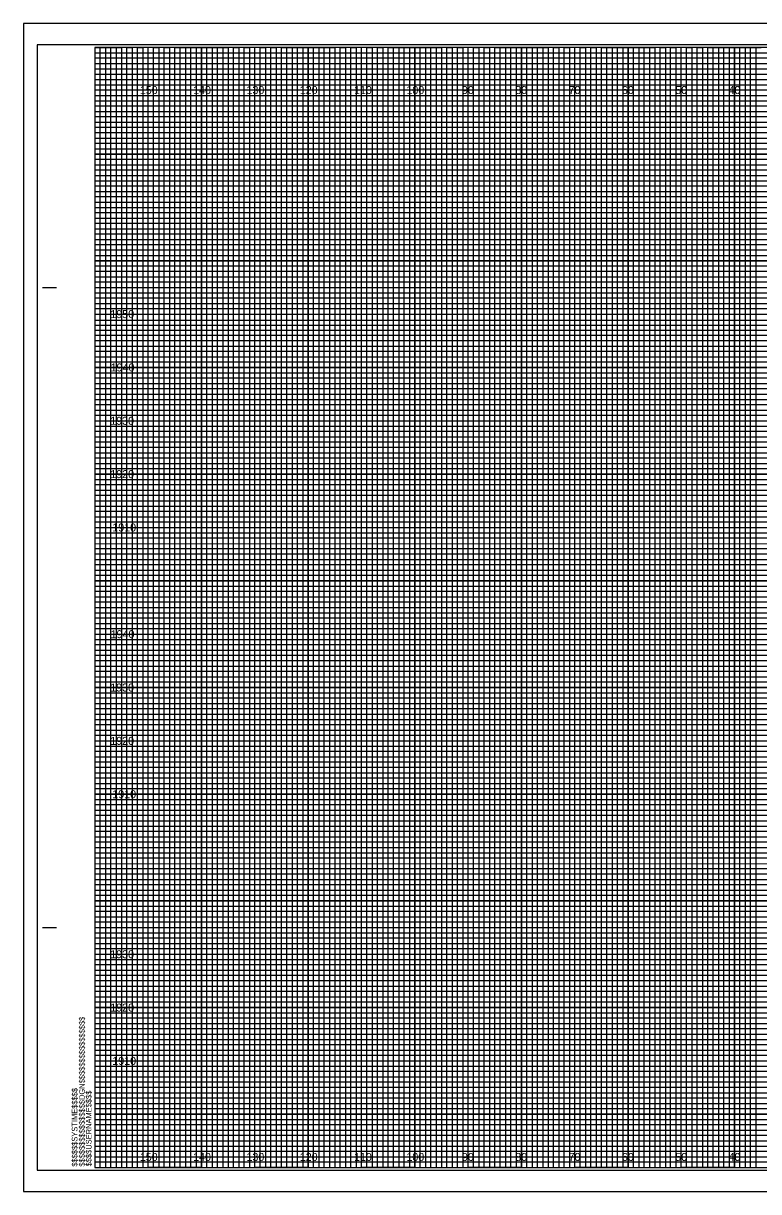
# Model space of a CAD drawing. Extents: x -13 to 323, y -4 to 214.
# Drawn here: x -13.4 to 124.5, y -4.5 to 214.5 of the extents above; entities that cross this region are included whole.
import ezdxf

# ---------------------------------------------------------------- set-up
doc = ezdxf.new("R2010")
doc.units = 0
for name, color, linetype in [('Prop XS Elevation Labels', 7, 'Continuous'), ('Prop XS Offset Labels', 7, 'Continuous'), ('Sheet Cross Section CELL', 7, 'Continuous'), ('Sheet Cross Section Grid Major CELL', 7, 'Continuous'), ('Sheet Cross Section Grid Middle CELL', 7, 'Continuous'), ('Sheet Cross Section Grid Minor 1 CELL', 7, 'Continuous'), ('Sheet Cross Section Grid Minor 2 CELL', 7, 'Continuous'), ('Sheet Cutting Line CELL', 7, 'Continuous'), ('Sheet DOT Grid CELL', 7, 'Continuous'), ('Sheet Plot Border Inside CELL', 7, 'Continuous'), ('Sheet Plot Border Outside CELL', 7, 'Continuous')]:
    doc.layers.add(name, color=color, linetype=linetype)

msp = doc.modelspace()

# ---------------------------------------------------------------- linework, layer by layer
at = {"layer": 'Sheet Cross Section CELL'}
for p, q in [((-9.8, 165), (-7.3, 165)), ((-9.7, 165), (-7.2, 165)), ((-9.8, 45), (-7.3, 45)), ((-9.7, 45), (-7.2, 45))]:
    msp.add_line(p, q, dxfattribs=at)
msp.add_lwpolyline([(320, 210), (0, 210), (0, 0), (320, 0)], close=True, dxfattribs=at)
at = {"layer": 'Sheet Cross Section Grid Major CELL'}
for p, q in [((10, 210), (0, 210)), ((10, 0), (10, 210)), ((30, 210), (20, 210)), ((20, 210), (20, 0)), ((30, 0), (30, 210)), ((50, 210), (40, 210)), ((40, 210), (40, 0)), ((50, 0), (50, 210)), ((70, 210), (60, 210)), ((60, 210), (60, 0)), ((70, 0), (70, 210)), ((90, 210), (80, 210)), ((80, 210), (80, 0)), ((90, 0), (90, 210)), ((110, 210), (100, 210)), ((100, 210), (100, 0)), ((110, 0), (110, 210)), ((130, 210), (120, 210)), ((120, 210), (120, 0)), ((20, 0), (10, 0)), ((40, 0), (30, 0)), ((60, 0), (50, 0)), ((80, 0), (70, 0)), ((100, 0), (90, 0)), ((120, 0), (110, 0))]:
    msp.add_line(p, q, dxfattribs=at)
for points in [[(0, 200), (320, 200), (320, 190), (0, 190)], [(0, 180), (320, 180), (320, 170), (0, 170)], [(0, 160), (320, 160), (320, 150), (0, 150)], [(0, 140), (320, 140), (320, 130), (0, 130)], [(0, 120), (320, 120), (320, 110), (0, 110)], [(0, 100), (320, 100), (320, 90), (0, 90)], [(0, 80), (320, 80), (320, 70), (0, 70)], [(0, 60), (320, 60), (320, 50), (0, 50)], [(0, 40), (320, 40), (320, 30), (0, 30)], [(0, 20), (320, 20), (320, 10), (0, 10)]]:
    msp.add_lwpolyline(points, dxfattribs=at)
at = {"layer": 'Sheet Cross Section Grid Middle CELL'}
for points in [[(0, 210), (5, 210), (5, 0), (15, 0), (15, 210), (25, 210), (25, 0), (35, 0), (35, 210), (45, 210), (45, 0), (55, 0), (55, 210), (65, 210), (65, 0), (75, 0), (75, 210), (85, 210), (85, 0), (95, 0), (95, 210), (105, 210), (105, 0), (115, 0), (115, 210), (125, 210)], [(0, 205), (275, 205)], [(0, 185), (320, 185), (320, 195), (0, 195)], [(0, 165), (320, 165), (320, 175), (0, 175)], [(0, 145), (320, 145), (320, 155), (0, 155)], [(0, 125), (320, 125), (320, 135), (0, 135)], [(0, 105), (320, 105), (320, 115), (0, 115)], [(0, 85), (320, 85), (320, 95), (0, 95)], [(0, 65), (320, 65), (320, 75), (0, 75)], [(0, 45), (320, 45), (320, 55), (0, 55)], [(0, 25), (320, 25), (320, 35), (0, 35)], [(0, 5), (320, 5), (320, 15), (0, 15)]]:
    msp.add_lwpolyline(points, dxfattribs=at)
at = {"layer": 'Sheet Cross Section Grid Minor 1 CELL'}
for p, q in [((0, 209), (260, 209)), ((260, 207.98), (0, 207.98)), ((0, 207.98), (0, 207)), ((0, 207), (260, 207)), ((260, 205.89), (0, 205.89)), ((0, 205.89), (0, 204)), ((0, 204), (320, 204))]:
    msp.add_line(p, q, dxfattribs=at)
for points in [[(0, 203), (270, 203), (320, 203), (320, 202), (0, 202)], [(0, 201), (320, 201), (320, 199), (0, 199)], [(0, 198), (320, 198), (320, 197), (0, 196.98)], [(0, 196), (320, 196), (320, 194), (0, 194)], [(0, 193), (320, 193), (320, 192), (0, 192)], [(0, 191), (320, 191), (320, 189), (0, 189)], [(0, 188), (320, 188), (320, 187), (0, 187)], [(0, 186), (320, 186), (320, 184), (0, 184)], [(0, 183), (320, 183), (320, 182), (0, 182)], [(0, 181), (320, 181), (320, 179), (0, 179)], [(0, 178), (320, 178), (320, 177), (0, 177)], [(0, 176), (320, 176), (320, 173.95), (320, 173), (320, 172), (0, 172)], [(0, 174), (320, 174), (320, 173), (0, 173)], [(0, 171), (320, 171), (320, 169), (0, 169.03)], [(0, 169.03), (320, 169), (320, 168), (0, 168)], [(0, 167), (320, 167), (320, 166), (0, 166)], [(0, 164), (320, 164), (320, 163), (0, 163)], [(0, 162), (320, 162), (320, 161), (0, 161)], [(-0.07, 158.89), (320, 158.89), (320, 157.88), (-0.07, 157.88)], [(0, 157), (320, 157), (320, 156), (0, 156)], [(0, 154), (320, 154), (320, 153), (0, 153)], [(0, 152), (320, 152), (320, 151), (0, 151)], [(0, 149), (320, 149), (320, 148), (0, 148)], [(0, 147), (320, 147), (320, 146), (0, 146)], [(0, 144), (320, 144), (320, 143), (0, 143)], [(0, 142), (320, 142), (320, 141), (0, 141)], [(0, 139), (320, 139), (319.99, 137.98), (0, 138)], [(0, 137), (320, 137), (320, 136), (0, 136)], [(0, 134), (320, 134), (320, 133), (0, 133)], [(0, 132), (320, 132), (320, 131), (0, 131)], [(0, 129), (320, 129), (320, 128), (0, 128)], [(0, 127), (320, 127), (320, 126), (0, 126)], [(0, 124), (320, 124), (320, 123), (0, 123)], [(0, 122), (320, 122), (320, 121), (0, 121)], [(0, 119), (320, 119), (320, 118), (0, 118)], [(0, 116.99), (320.07, 116.91), (320, 116), (0, 116)], [(0, 114), (320, 114), (320, 113), (0, 113)], [(0, 112), (320, 112), (320, 111), (0, 111)], [(0, 109), (320, 109), (320, 108), (0, 108)], [(0, 107), (320, 107), (320, 106), (0, 106)], [(0, 104), (320, 104), (320, 103), (0, 103)], [(0, 102), (320, 102), (320, 101), (0, 101)], [(0, 99), (320, 99), (320, 98), (0, 98)], [(0, 97), (320, 97), (320, 96), (0, 96)], [(0, 94), (320, 94), (320, 93), (0, 93)], [(0, 92), (320, 92), (320, 91), (0, 91)], [(0, 89), (320, 89), (320, 88), (0, 88)], [(0, 87), (320, 87), (320, 86), (0, 86)], [(0, 84), (320, 84), (320, 83), (0, 83)], [(0, 82), (320, 82), (320, 81), (0, 81)], [(0, 79), (320, 79), (319.99, 77.98), (0, 78)], [(0, 77), (320, 77), (320, 76), (0, 76)], [(0, 74), (320, 74), (320, 73), (0, 73)], [(0, 72), (320, 72), (320, 71), (0, 71)], [(0, 69), (320, 69), (320, 68), (0, 68)], [(0, 67), (320, 67), (320, 66), (0, 66)], [(0, 64), (320, 64), (320, 63), (0, 63)], [(0, 62), (320, 62), (320, 61), (0, 61)], [(0, 59), (320, 59), (320, 58), (0, 58)], [(0, 56.99), (320.07, 56.91), (320, 56), (0, 56)], [(0, 54), (320, 54), (320, 53), (0, 53)], [(0, 52), (320, 52), (320, 51), (0, 51)], [(0, 49), (320, 49), (320, 48), (0, 48)], [(0, 47), (320, 47), (320, 46), (0, 46)], [(0, 44), (320, 44), (320, 43), (0, 43)], [(0, 42), (320, 42), (320, 41), (0, 41)], [(0, 39), (320, 39), (320, 38), (0, 38)], [(0, 37), (320, 37), (320, 36), (0, 36)], [(0, 34), (320, 34), (320, 33), (0, 33)], [(0, 32), (320, 32), (320, 31), (0, 31)], [(0, 29), (320, 29), (320, 28), (0, 28)], [(0, 27), (320, 27), (320, 26), (0, 26)], [(0, 24), (320, 24), (320, 23), (0, 23)], [(0, 22), (320, 22), (320, 21), (0, 21)], [(0, 19), (320, 19), (320, 18), (0, 18)], [(0, 17), (320, 17), (320, 16), (0, 16)], [(0, 14), (320, 14), (320, 13), (0, 13)], [(0, 12), (320, 12), (320, 11), (0, 11)], [(0, 9), (320, 9), (320, 8), (0, 8)], [(0, 7), (320, 7), (320, 6), (0, 6)], [(0, 4), (320, 4), (320, 3), (0, 3)], [(0, 2), (320, 2), (320, 1), (0, 1)]]:
    msp.add_lwpolyline(points, dxfattribs=at)
at = {"layer": 'Sheet Cross Section Grid Minor 2 CELL'}
for points in [[(0, 0), (1, 0), (1, 210), (2, 210), (2, 0)], [(2, 0), (3, 0), (3, 210), (4, 210), (4, 0)], [(5, 0), (6, 0), (6, 210), (7, 210), (7, 0)], [(7, 0), (8, 0), (8, 210), (9, 210), (9, 0)], [(10, 0), (11, 0), (11, 210), (12, 210), (12, 0)], [(12, 0), (13, 0), (13, 210), (14, 210), (14, 0)], [(15, 0), (16, 0), (16, 210), (17, 210), (17, 0)], [(17, 0), (18, 0), (18, 210), (19, 210), (19, 0)], [(20, 0), (21, 0), (21, 210), (22, 210), (22, 0)], [(22, 0), (23, 0), (23, 210), (24, 210), (24, 0)], [(25, 0), (26, 0), (26, 210), (27, 210), (27, 0)], [(27, 0), (28, 0), (28, 210), (29, 210), (29, 0)], [(30, 0), (31, 0), (31, 210), (32, 210), (32, 0)], [(32, 0), (33, 0), (33, 210), (34, 210), (34, 0)], [(35, 0), (36, 0), (36, 210), (37, 210), (37, 0)], [(37, 0), (38, 0), (38, 210), (39, 210), (39, 0)], [(40, 0), (41, 0), (41, 210), (42, 210), (42, 0)], [(42, 0), (43, 0), (43, 210), (44, 210), (44, 0)], [(45, 0), (46, 0), (46, 210), (47, 210), (47, 0)], [(47, 0), (48, 0), (48, 210), (49, 210), (49, 0)], [(50, 0), (51, 0), (51, 210), (52, 210), (52, 0)], [(52, 0), (53, 0), (53, 210), (54, 210), (54, 0)], [(55, 0), (56, 0), (56, 210), (57, 210), (57, 0)], [(57, 0), (58, 0), (58, 210), (59, 210), (59, 0)], [(60, 0), (61, 0), (61, 210), (62, 210), (62, 0)], [(62, 0), (63, 0), (63, 210), (64, 210), (64, 0)], [(65, 0), (66, 0), (66, 210), (67, 210), (67, 0)], [(67, 0), (68, 0), (68, 210), (69, 210), (69, 0)], [(70, 0), (71, 0), (71, 210), (72, 210), (72, 0)], [(72, 0), (73, 0), (73, 210), (74, 210), (74, 0)], [(75, 0), (76, 0), (76, 210), (77, 210), (77, 0)], [(77, 0), (78, 0), (78, 210), (79, 210), (79, 0)], [(80, 0), (81, 0), (81, 210), (82, 210), (82, 0)], [(82, 0), (83, 0), (83, 210), (84, 210), (84, 0)], [(85, 0), (86, 0), (86, 210), (87, 210), (87, 0)], [(87, 0), (88, 0), (88, 210), (89, 210), (89, 0)], [(90, 0), (91, 0), (91, 210), (92, 210), (92, 0)], [(92, 0), (93, 0), (93, 210), (94, 210), (94, 0)], [(95, 0), (96, 0), (96, 210), (97, 210), (97, 0)], [(97, 0), (98, 0), (98, 210), (99, 210), (99, 0)], [(100, 0), (101, 0), (101, 210), (102, 210), (102, 0)], [(102, 0), (103, 0), (103, 210), (104, 210), (104, 0)], [(105, 0), (106, 0), (106, 210), (107, 210), (107, 0)], [(107, 0), (108, 0), (108, 210), (109, 210), (109, 0)], [(110, 0), (111, 0), (111, 210), (112, 210), (112, 0)], [(112, 0), (113, 0), (113, 210), (114, 210), (114, 0)], [(115, 0), (116, 0), (116, 210), (117, 210), (117, 0)], [(117, 0), (118, 0), (118, 210), (119, 210), (119, 0)], [(120, 0), (121, 0), (121, 210), (122, 210), (122, 0)], [(122, 0), (123, 0), (123, 210), (124, 210), (124, 0)]]:
    msp.add_lwpolyline(points, dxfattribs=at)
at = {"layer": 'Sheet Cutting Line CELL'}
for p, q in [((323.3, 214.5), (-13.4, 214.5)), ((-13.4, 214.5), (-13.4, -4.5)), ((-13.4, -4.5), (323.3, -4.5))]:
    msp.add_line(p, q, dxfattribs=at)
at = {"layer": 'Sheet DOT Grid CELL'}
for p, q in [((10, 0), (10, 210)), ((20, 0), (20, 210)), ((30, 0), (30, 210)), ((40, 0), (40, 210)), ((50, 0), (50, 210)), ((60, 0), (60, 210)), ((70, 0), (70, 210)), ((80, 0), (80, 210)), ((90, 0), (90, 210)), ((100, 0), (100, 210)), ((110, 0), (110, 210)), ((120, 0), (120, 210)), ((0, 200), (320, 200)), ((0, 190), (320, 190)), ((0, 180), (320, 180)), ((0, 170), (320, 170)), ((0, 160), (320, 160)), ((0, 150), (320, 150)), ((0, 140), (320, 140)), ((0, 130), (320, 130)), ((0, 120), (320, 120)), ((0, 110), (320, 110)), ((0, 100), (320, 100)), ((0, 90), (320, 90)), ((0, 80), (320, 80)), ((0, 70), (320, 70)), ((0, 60), (320, 60)), ((0, 50), (320, 50)), ((0, 40), (320, 40)), ((0, 30), (320, 30)), ((0, 20), (320, 20)), ((0, 10), (320, 10))]:
    msp.add_line(p, q, dxfattribs=at)
at = {"layer": 'Sheet Plot Border Inside CELL'}
msp.add_lwpolyline([(-10.8, -0.5), (322.4, -0.5), (322.4, 210.5), (-10.8, 210.5)], close=True, dxfattribs=at)
at = {"layer": 'Sheet Plot Border Outside CELL'}
msp.add_lwpolyline([(-13.4, -4.5), (323.3, -4.5), (323.3, 214.5), (-13.4, 214.5)], close=True, dxfattribs=at)

# ---------------------------------------------------------------- texts
at = {"layer": 'Prop XS Elevation Labels'}
for s, p in [('1950', (2.92, 159.25)), ('1940', (2.97, 149.25)), ('1930', (2.89, 139.25)), ('1920', (2.9, 129.25)), ('1910', (3.28, 119.25)), ('1940', (2.97, 99.25)), ('1930', (2.89, 89.25)), ('1920', (2.9, 79.25)), ('1910', (3.28, 69.25)), ('1930', (2.89, 39.25)), ('1920', (2.9, 29.25)), ('1910', (3.28, 19.25))]:
    msp.add_text(s, height=1.5, dxfattribs=at).set_placement(p)
at = {"layer": 'Prop XS Offset Labels'}
for s, p in [('150', (8.44, 201.25)), ('140', (18.44, 201.25)), ('130', (28.44, 201.25)), ('120', (38.44, 201.25)), ('110', (48.62, 201.25)), ('100', (58.44, 201.25)), ('90', (68.86, 201.25)), ('80', (78.86, 201.25)), ('70', (88.86, 201.25)), ('60', (98.86, 201.25)), ('50', (108.86, 201.25)), ('40', (118.86, 201.25)), ('150', (8.44, 1.25)), ('140', (18.44, 1.25)), ('130', (28.44, 1.25)), ('120', (38.44, 1.25)), ('110', (48.62, 1.25)), ('100', (58.44, 1.25)), ('90', (68.86, 1.25)), ('80', (78.86, 1.25)), ('70', (88.86, 1.25)), ('60', (98.86, 1.25)), ('50', (108.86, 1.25)), ('40', (118.86, 1.25))]:
    msp.add_text(s, height=1.5, dxfattribs=at).set_placement(p)
at = {"layer": 'Sheet Cross Section CELL'}
for s, p in [('$$$$$$$$$$$$$$$$DGN$$$$$$$$$$$$$$$$', (-1.88, 0.18)), ('$$$$$$SYSTIME$$$$$', (-3.26, 0.18)), ('$$$$USERNAME$$$$', (-0.62, 0.23))]:
    msp.add_text(s, height=1.05, rotation=90, dxfattribs=at).set_placement(p)

doc.saveas('drawing.dxf')
